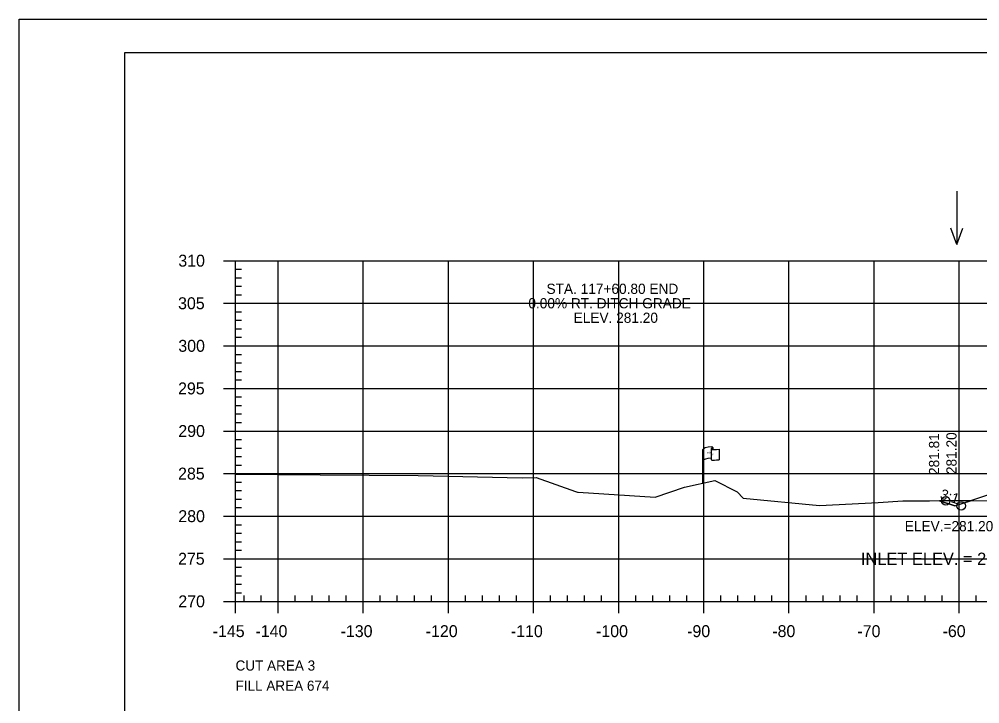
# Model space of a CAD drawing. Extents: x 1370843 to 1371177, y 380307 to 382654.
# Drawn here: x 1370843.3 to 1370956.1, y 381720.5 to 381800.8 of the extents above; entities that cross this region are included whole.
import ezdxf

# ---------------------------------------------------------------- set-up
doc = ezdxf.new("R2010")
doc.units = 0
for name, color, linetype in [('R_Axis', 7, 'Continuous'), ('R_Axis Annot', 7, 'Continuous'), ('R_Border', 7, 'Continuous'), ('R_Border Notes', 7, 'Continuous'), ('R_Exist Surface', 7, 'Continuous'), ('R_Fin Surface', 7, 'Continuous'), ('R_Fin Surface Annot', 7, 'Continuous'), ('R_Grid', 7, 'Continuous'), ('R_No Plot', 7, 'Continuous'), ('R_ROW', 7, 'Continuous'), ('R_Water Annot', 7, 'Continuous')]:
    doc.layers.add(name, color=color, linetype=linetype)

msp = doc.modelspace()

# ---------------------------------------------------------------- linework, layer by layer
at = {"layer": 'R_Axis'}
for p, q in [((1370867.31, 381772.48), (1370868.71, 381772.48)), ((1370868.71, 381732.48), (1370868.71, 381772.48)), ((1370868.71, 381771.48), (1370869.41, 381771.48)), ((1370868.71, 381770.48), (1370869.41, 381770.48)), ((1370868.71, 381769.48), (1370869.41, 381769.48)), ((1370868.71, 381768.48), (1370869.41, 381768.48)), ((1370867.31, 381767.48), (1370868.71, 381767.48)), ((1370868.71, 381766.48), (1370869.41, 381766.48)), ((1370868.71, 381765.48), (1370869.41, 381765.48)), ((1370868.71, 381764.48), (1370869.41, 381764.48)), ((1370868.71, 381763.48), (1370869.41, 381763.48)), ((1370867.31, 381762.48), (1370868.71, 381762.48)), ((1370868.71, 381761.48), (1370869.41, 381761.48)), ((1370868.71, 381760.48), (1370869.41, 381760.48)), ((1370868.71, 381759.48), (1370869.41, 381759.48)), ((1370868.71, 381758.48), (1370869.41, 381758.48)), ((1370867.31, 381757.48), (1370868.71, 381757.48)), ((1370868.71, 381756.48), (1370869.41, 381756.48)), ((1370868.71, 381755.48), (1370869.41, 381755.48)), ((1370868.71, 381754.48), (1370869.41, 381754.48)), ((1370868.71, 381753.48), (1370869.41, 381753.48)), ((1370867.31, 381752.48), (1370868.71, 381752.48)), ((1370868.71, 381751.48), (1370869.41, 381751.48)), ((1370868.71, 381750.48), (1370869.41, 381750.48)), ((1370868.71, 381749.48), (1370869.41, 381749.48)), ((1370868.71, 381748.48), (1370869.41, 381748.48)), ((1370867.31, 381747.48), (1370868.71, 381747.48)), ((1370868.71, 381746.48), (1370869.41, 381746.48)), ((1370868.71, 381745.48), (1370869.41, 381745.48)), ((1370868.71, 381744.48), (1370869.41, 381744.48)), ((1370867.31, 381742.48), (1370868.71, 381742.48)), ((1370868.71, 381743.48), (1370869.41, 381743.48)), ((1370868.71, 381741.48), (1370869.41, 381741.48)), ((1370868.71, 381740.48), (1370869.41, 381740.48)), ((1370868.71, 381739.48), (1370869.41, 381739.48)), ((1370868.71, 381738.48), (1370869.41, 381738.48)), ((1370867.31, 381737.48), (1370868.71, 381737.48)), ((1370868.71, 381736.48), (1370869.41, 381736.48)), ((1370868.71, 381735.48), (1370869.41, 381735.48)), ((1370868.71, 381734.48), (1370869.41, 381734.48)), ((1370868.71, 381733.48), (1370869.41, 381733.48)), ((1370867.31, 381732.48), (1370868.71, 381732.48)), ((1370868.71, 381732.48), (1370868.71, 381733.18)), ((1370868.71, 381732.48), (1371158.71, 381732.48)), ((1370868.71, 381731.08), (1370868.71, 381732.48)), ((1370869.71, 381732.48), (1370869.71, 381733.18)), ((1370871.71, 381732.48), (1370871.71, 381733.18)), ((1370873.71, 381731.08), (1370873.71, 381732.48)), ((1370875.71, 381732.48), (1370875.71, 381733.18)), ((1370877.71, 381732.48), (1370877.71, 381733.18)), ((1370879.71, 381732.48), (1370879.71, 381733.18)), ((1370881.71, 381732.48), (1370881.71, 381733.18)), ((1370883.71, 381731.08), (1370883.71, 381732.48)), ((1370885.71, 381732.48), (1370885.71, 381733.18)), ((1370887.71, 381732.48), (1370887.71, 381733.18)), ((1370889.71, 381732.48), (1370889.71, 381733.18)), ((1370891.71, 381732.48), (1370891.71, 381733.18)), ((1370893.71, 381731.08), (1370893.71, 381732.48)), ((1370895.71, 381732.48), (1370895.71, 381733.18)), ((1370897.71, 381732.48), (1370897.71, 381733.18)), ((1370899.71, 381732.48), (1370899.71, 381733.18)), ((1370901.71, 381732.48), (1370901.71, 381733.18)), ((1370903.71, 381731.08), (1370903.71, 381732.48)), ((1370905.71, 381732.48), (1370905.71, 381733.18)), ((1370907.71, 381732.48), (1370907.71, 381733.18)), ((1370909.71, 381732.48), (1370909.71, 381733.18)), ((1370911.71, 381732.48), (1370911.71, 381733.18)), ((1370913.71, 381731.08), (1370913.71, 381732.48)), ((1370915.71, 381732.48), (1370915.71, 381733.18)), ((1370917.71, 381732.48), (1370917.71, 381733.18)), ((1370919.71, 381732.48), (1370919.71, 381733.18)), ((1370921.71, 381732.48), (1370921.71, 381733.18)), ((1370923.71, 381731.08), (1370923.71, 381732.48)), ((1370925.71, 381732.48), (1370925.71, 381733.18)), ((1370927.71, 381732.48), (1370927.71, 381733.18)), ((1370929.71, 381732.48), (1370929.71, 381733.18)), ((1370931.71, 381732.48), (1370931.71, 381733.18)), ((1370933.71, 381731.08), (1370933.71, 381732.48)), ((1370935.71, 381732.48), (1370935.71, 381733.18)), ((1370937.71, 381732.48), (1370937.71, 381733.18)), ((1370939.71, 381732.48), (1370939.71, 381733.18)), ((1370941.71, 381732.48), (1370941.71, 381733.18)), ((1370943.71, 381731.08), (1370943.71, 381732.48)), ((1370945.71, 381732.48), (1370945.71, 381733.18)), ((1370947.71, 381732.48), (1370947.71, 381733.18)), ((1370949.71, 381732.48), (1370949.71, 381733.18)), ((1370951.71, 381732.48), (1370951.71, 381733.18)), ((1370953.71, 381731.08), (1370953.71, 381732.48)), ((1370955.71, 381732.48), (1370955.71, 381733.18))]:
    msp.add_line(p, q, dxfattribs=at)
at = {"layer": 'R_Border'}
for p, q in [((1370855.71, 381796.94), (1371171.89, 381796.94)), ((1370855.71, 381591.48), (1370855.71, 381796.94))]:
    msp.add_line(p, q, dxfattribs=at)
at = {"layer": 'R_Exist Surface'}
msp.add_lwpolyline([(1370868.71, 381747.4), (1370878.64, 381747.32), (1370890.16, 381747.27), (1370902.37, 381747), (1370904.02, 381747.02), (1370908.62, 381745.38), (1370908.88, 381745.29), (1370908.93, 381745.3), (1370908.97, 381745.3), (1370918.01, 381744.7), (1370921.43, 381745.87), (1370925, 381746.65), (1370927.61, 381745.35), (1370928.34, 381744.59), (1370937.3, 381743.75), (1370944.2, 381744.1), (1370947.1, 381744.27), (1370950.23, 381744.28), (1370965.84, 381744.31)], dxfattribs=at)
at = {"layer": 'R_Fin Surface'}
msp.add_lwpolyline([(1370951.37, 381744.28), (1370953.19, 381743.68), (1370983.56, 381753.8), (1370984.56, 381753.8), (1370990.77, 381754.69), (1371000.71, 381755.93), (1371002.71, 381756.01), (1371013.71, 381756.23), (1371024.71, 381756.01), (1371026.71, 381755.93), (1371035.2, 381754.72), (1371043.6, 381753.6), (1371043.6, 381753.6), (1371044.6, 381753.6), (1371074.22, 381743.48), (1371076.33, 381744.18)], dxfattribs=at)
at = {"layer": 'R_Grid'}
for p, q in [((1370868.71, 381772.48), (1371158.71, 381772.48)), ((1370868.71, 381732.48), (1370868.71, 381772.48)), ((1370873.71, 381732.48), (1370873.71, 381772.48)), ((1370883.71, 381732.48), (1370883.71, 381772.48)), ((1370893.71, 381732.48), (1370893.71, 381772.48)), ((1370903.71, 381732.48), (1370903.71, 381772.48)), ((1370913.71, 381732.48), (1370913.71, 381772.48)), ((1370923.71, 381732.48), (1370923.71, 381772.48)), ((1370933.71, 381732.48), (1370933.71, 381772.48)), ((1370943.71, 381732.48), (1370943.71, 381772.48)), ((1370953.71, 381732.48), (1370953.71, 381772.48)), ((1370868.71, 381767.48), (1371158.71, 381767.48)), ((1370868.71, 381762.48), (1371158.71, 381762.48)), ((1370868.71, 381757.48), (1371158.71, 381757.48)), ((1370868.71, 381752.48), (1371158.71, 381752.48)), ((1370868.71, 381747.48), (1371158.71, 381747.48)), ((1370868.71, 381742.48), (1371158.71, 381742.48)), ((1370868.71, 381737.48), (1371158.71, 381737.48)), ((1370868.71, 381732.48), (1371158.71, 381732.48))]:
    msp.add_line(p, q, dxfattribs=at)
at = {"layer": 'R_No Plot'}
for p, q in [((1370843.31, 381800.83), (1371176.64, 381800.83)), ((1370953.19, 381743.68), (1370951.37, 381744.28))]:
    msp.add_line(p, q, dxfattribs=at)
for points in [[(1370843.3, 381800.83), (1371176.64, 381800.83), (1371176.64, 381587.49), (1370843.3, 381587.49)], [(1371089.63, 381796.94), (1371089.63, 381787.06), (1371125.36, 381787.06), (1371125.36, 381784.14), (1371148.56, 381784.14), (1371148.56, 381759.8), (1371171.89, 381759.8), (1371171.89, 381591.48), (1370855.71, 381591.48), (1370855.71, 381796.94)], [(1370951.37, 381744.28), (1370953.19, 381743.68), (1370955.03, 381744.29)]]:
    msp.add_lwpolyline(points, close=True, dxfattribs=at)
msp.add_lwpolyline([(1370997.38, 381754.82), (1370990.77, 381754.69), (1370984.56, 381753.8), (1370983.56, 381753.8), (1370955.03, 381744.29), (1370965.84, 381744.31), (1370983, 381746.08), (1370984.82, 381746.41), (1370985.8, 381746.41), (1370989.19, 381747.73), (1370992.32, 381747.64), (1370993.46, 381747.64)], dxfattribs=at)
for centre in [(1370952.12, 381744.28), (1370953.94, 381743.68)]:
    msp.add_circle(centre, 0.5, dxfattribs=at)
at = {"layer": 'R_ROW'}
for p, q in [((1370924.58, 381750.39), (1370924.58, 381750.38)), ((1370924.58, 381750.38), (1370924.58, 381749.15)), ((1370924.75, 381750.55), (1370924.75, 381750.3)), ((1370925.52, 381750.35), (1370925.52, 381749.11)), ((1370923.59, 381746.34), (1370923.59, 381750.29))]:
    msp.add_line(p, q, dxfattribs=at)
for centre, radius, start, end in [((1370924.66, 381750.39), 0.078, 88.6458, 274.2828), ((1370924.67, 381750.55), 0.0783, 263.0712, 93.9564), ((1370924.66, 381749.15), 0.0783, 180, 273.9564)]:
    msp.add_arc(centre, radius, start, end, dxfattribs=at)
for centre, major_axis, ratio, start_param, end_param in [((1370925.17, 381750.34), (-1.58, -0.04), 0.19887, 5.030368, 6.283185), ((1370925.88, 381750.45), (-1.23, -0.13), 0.052933, 0.159456, 1.268315), ((1370925.16, 381749.02), (-1.58, -0.04), 0.19887, 5.083035, 6.194897), ((1370925.88, 381749.21), (-1.23, -0.13), 0.052933, 0.159456, 1.268315)]:
    msp.add_ellipse(centre, major_axis=major_axis, ratio=ratio, start_param=start_param, end_param=end_param, dxfattribs=at)
at = {"layer": 'R_Water Annot'}
for p, q in [((1370953.43, 381780.66), (1370953.43, 381774.38)), ((1370953.43, 381774.38), (1370952.73, 381776.3)), ((1370953.43, 381774.38), (1370954.13, 381776.3))]:
    msp.add_line(p, q, dxfattribs=at)

# ---------------------------------------------------------------- texts
at = {"layer": 'R_Axis Annot'}
for s, p in [('310', (1370861.99, 381771.78)), ('305', (1370861.96, 381766.78)), ('300', (1370861.99, 381761.78)), ('295', (1370861.96, 381756.78)), ('290', (1370861.99, 381751.78)), ('285', (1370861.96, 381746.78)), ('280', (1370861.99, 381741.78)), ('275', (1370861.96, 381736.78)), ('270', (1370861.99, 381731.78)), ('-145', (1370866.03, 381728.28)), ('-140', (1370871.05, 381728.28)), ('-130', (1370881.05, 381728.28)), ('-120', (1370891.05, 381728.28)), ('-110', (1370901.05, 381728.28)), ('-100', (1370911.05, 381728.28)), ('-90', (1370921.75, 381728.28)), ('-80', (1370931.75, 381728.28)), ('-70', (1370941.75, 381728.28)), ('-60', (1370951.75, 381728.28))]:
    msp.add_text(s, height=1.4, dxfattribs=at).set_placement(p)
at = {"layer": 'R_Border Notes'}
msp.add_text('281.81', height=1.2, rotation=90, dxfattribs=at).set_placement((1370951.35, 381747.31))
for s, height, p in [('CUT AREA 3', 1.187, (1370868.71, 381724.35)), ('FILL AREA 674', 1.1875, (1370868.71, 381721.98))]:
    msp.add_text(s, height=height, dxfattribs=at).set_placement(p)
at = {"layer": 'R_Fin Surface Annot'}
for s, rotation, p in [('281.20', 90, (1370953.39, 381747.42)), ('3:1', 341.5651, (1370951.36, 381744.58))]:
    msp.add_text(s, height=1.2, rotation=rotation, dxfattribs=at).set_placement(p)
at = {"layer": 'R_ROW'}
for s, height, rotation, p in [('DWB 11-9-07', 0.001, 90, (1370924.75, 381750.3)), ('R ', 0.2, 9.9884, (1370924.11, 381749.8)), (' O', 0.2, 9.9884, (1370924.25, 381749.84)), ('W', 0.2, 351.1788, (1370924.58, 381749.67)), ('DWB 11-9-07', 0.001, 5.0717, (1370925.51, 381749.11)), ('DWB 11-9-07', 0.001, 90, (1370923.59, 381746.34))]:
    msp.add_text(s, height=height, rotation=rotation, dxfattribs=at).set_placement(p)
at = {"layer": 'R_Water Annot'}
for s, height, p in [('STA. 117+60.80 END', 1.2, (1370905.23, 381768.58)), ('0.00% RT. DITCH GRADE', 1.2, (1370903.1, 381766.88)), ('ELEV. 281.20', 1.2, (1370908.42, 381765.18)), ('ELEV.=281.20', 1.2, (1370947.31, 381740.71)), ('INLET ELEV. = 281.20', 1.44, (1370942.16, 381736.76))]:
    msp.add_text(s, height=height, dxfattribs=at).set_placement(p)

doc.saveas('drawing.dxf')
